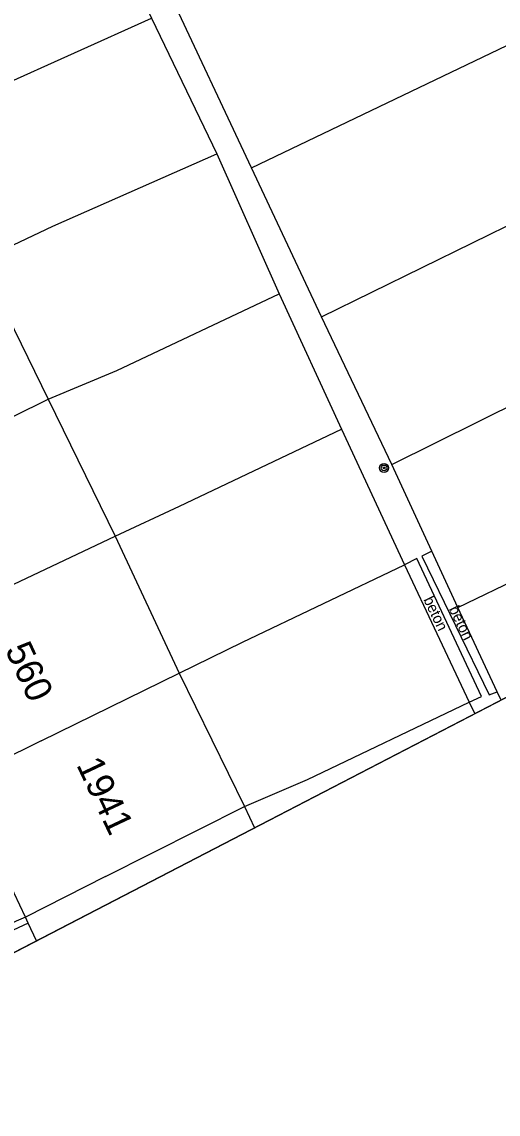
# Model space of a CAD drawing. Extents: x -493753 to -49290, y -1127285 to -112654.
# Drawn here: x -493173.4 to -493146.9, y -1127103.7 to -1127042.8 of the extents above; entities that cross this region are included whole.
import ezdxf

# ---------------------------------------------------------------- set-up
doc = ezdxf.new("R2010")
doc.units = 0
for name, color, linetype in [('Vrstva 1', 7, 'Continuous'), ('Vrstva 10', 7, 'Continuous'), ('Vrstva 11', 7, 'Continuous'), ('Vrstva 25', 7, 'Continuous'), ('Vrstva 40', 7, 'Continuous'), ('Vrstva 43', 7, 'Continuous'), ('Vrstva 5', 7, 'Continuous'), ('Vrstva 60', 7, 'Continuous'), ('Vrstva 7', 7, 'Continuous')]:
    doc.layers.add(name, color=color, linetype=linetype)

msp = doc.modelspace()

# ---------------------------------------------------------------- linework, layer by layer
at = {"layer": 'Vrstva 1'}
msp.add_lwpolyline([(-493753.129, -1126773.634), (-493540.881, -1127284.865), (-492737.61, -1126868.64), (-492950.39, -1126535.73)], dxfattribs=at)
at = {"layer": 'Vrstva 10'}
for points in [[(-493148.49, -1127080.74), (-493147.8, -1127080.43), (-493151.41, -1127072.73), (-493152.1, -1127073.08)], [(-493150.58, -1127072.32), (-493151.14, -1127072.61), (-493147.38, -1127080.34), (-493146.93, -1127080.17)], [(-493173.24, -1127092.72), (-493173.76, -1127092.95), (-493178.1, -1127095.11)], [(-493173.08, -1127093.06), (-493173.92, -1127093.45), (-493177.98, -1127095.38)]]:
    msp.add_lwpolyline(points, dxfattribs=at)
at = {"layer": 'Vrstva 11'}
for points in [[(-493175.77, -1127056.12), (-493171.71, -1127054.21)], [(-493175.77, -1127056.12), (-493171.97, -1127063.84)], [(-493171.97, -1127063.84), (-493168.14, -1127062.25)], [(-493179.54, -1127067.59), (-493171.97, -1127063.84)], [(-493171.97, -1127063.84), (-493168.24, -1127071.48)], [(-493168.24, -1127071.48), (-493164.65, -1127069.82)], [(-493176.03, -1127075.16), (-493168.24, -1127071.48)], [(-493168.24, -1127071.48), (-493164.67, -1127079.12)], [(-493164.67, -1127079.12), (-493161.13, -1127077.39)], [(-493172.36, -1127082.9), (-493164.67, -1127079.12)], [(-493164.67, -1127079.12), (-493161.03, -1127086.56)], [(-493161.03, -1127086.56), (-493157.51, -1127085.05)], [(-493168.78, -1127090.47), (-493161.03, -1127086.56)], [(-493161.03, -1127086.56), (-493160.468, -1127087.75)]]:
    msp.add_lwpolyline(points, dxfattribs=at)
at = {"layer": 'Vrstva 25'}
for radius in [0.25, 0.158, 0.05]:
    msp.add_circle((-493153.24, -1127067.68), radius, dxfattribs=at)
at = {"layer": 'Vrstva 5'}
for p, q in [((-493172.36, -1127082.9), (-493176.85, -1127085.1)), ((-493168.78, -1127090.47), (-493173.24, -1127092.72))]:
    msp.add_line(p, q, dxfattribs=at)
for points in [[(-493173.24, -1127092.72), (-493176.72, -1127085.37), (-493176.85, -1127085.1)], [(-493172.614, -1127094.043), (-493173.08, -1127093.06), (-493173.24, -1127092.72)]]:
    msp.add_lwpolyline(points, dxfattribs=at)
at = {"layer": 'Vrstva 60'}
msp.add_lwpolyline([(-493659.148, -1127000), (-493540.881, -1127284.865), (-493125, -1127069.371)], dxfattribs=at)
at = {"layer": 'Vrstva 7'}
for p, q in [((-493175.32, -1127046.71), (-493166.2, -1127042.6)), ((-493160.63, -1127050.95), (-493145.21, -1127043.55)), ((-493171.71, -1127054.21), (-493162.56, -1127050.16)), ((-493156.73, -1127059.26), (-493141.35, -1127051.71)), ((-493168.14, -1127062.25), (-493159.09, -1127057.98)), ((-493152.8, -1127067.49), (-493137.5, -1127059.87)), ((-493164.65, -1127069.82), (-493155.62, -1127065.52)), ((-493149.13, -1127075.46), (-493133.65, -1127068.04)), ((-493161.13, -1127077.39), (-493152.1, -1127073.08)), ((-493157.51, -1127085.05), (-493148.49, -1127080.74))]:
    msp.add_line(p, q, dxfattribs=at)
for points in [[(-493177.34, -1127018.91), (-493173.54, -1127026.98), (-493170.03, -1127034.42), (-493169.18, -1127036.24), (-493168.49, -1127037.71), (-493166.2, -1127042.6), (-493162.56, -1127050.16)], [(-493152.8, -1127067.49), (-493156.73, -1127059.26), (-493160.63, -1127050.95), (-493165.26, -1127041.09), (-493166.12, -1127039.26), (-493169.05, -1127033.07)], [(-493162.56, -1127050.16), (-493159.09, -1127057.98), (-493155.62, -1127065.52)], [(-493155.62, -1127065.52), (-493152.1, -1127073.08)], [(-493146.717, -1127080.624), (-493146.93, -1127080.17), (-493149.13, -1127075.46), (-493150.58, -1127072.32), (-493152.8, -1127067.49)], [(-493152.1, -1127073.08), (-493148.49, -1127080.74)], [(-493148.49, -1127080.74), (-493148.183, -1127081.384)]]:
    msp.add_lwpolyline(points, dxfattribs=at)

# ---------------------------------------------------------------- texts
at = {"layer": 'Vrstva 40'}
for p in [(-493151.059, -1127075.02), (-493149.639, -1127075.54)]:
    msp.add_text('beton', height=0.6, rotation=295.63819, dxfattribs=at).set_placement(p)
at = {"layer": 'Vrstva 43'}
for s, rotation, p in [('560', 294.87365, (-493174.395, -1127077.817)), ('1941', 295.30522, (-493170.417, -1127084.23))]:
    msp.add_text(s, height=1.5, rotation=rotation, dxfattribs=at).set_placement(p)

doc.saveas('drawing.dxf')
